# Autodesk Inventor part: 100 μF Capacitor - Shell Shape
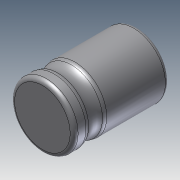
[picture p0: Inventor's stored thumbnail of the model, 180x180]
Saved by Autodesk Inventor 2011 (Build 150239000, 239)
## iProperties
Created: 2013-03
Part Number: 100 μF Capacitor - Shell Shape
Document SubType Name: Modeling
Designer: Lance
Density: 1 g/cm^3
Author: Lance
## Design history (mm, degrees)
node "100 uF Capacitor - Basic Shape" dims "d0" = 10
shell "Shell1" dims "d1" = 0.2
feature "Solid1::100 μF Capacitor - Basic Shape.ipt" dims "d0" = 10
tag "TaggingFeature1"
body "Solid1"
